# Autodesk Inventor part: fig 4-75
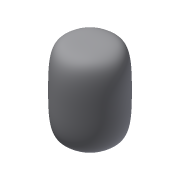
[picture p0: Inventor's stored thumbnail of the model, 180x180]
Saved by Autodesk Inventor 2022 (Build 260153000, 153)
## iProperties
Created: 2012-07
Part Number: fig 4-75
Material: Generic
Document SubType Name: Modeling
Designer: CADCIM
Density: 1 g/cm^3
Appearance: Default
Author: CADCIM
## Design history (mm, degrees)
feature "Form1"
body "Solid1"
body "Solid2"
